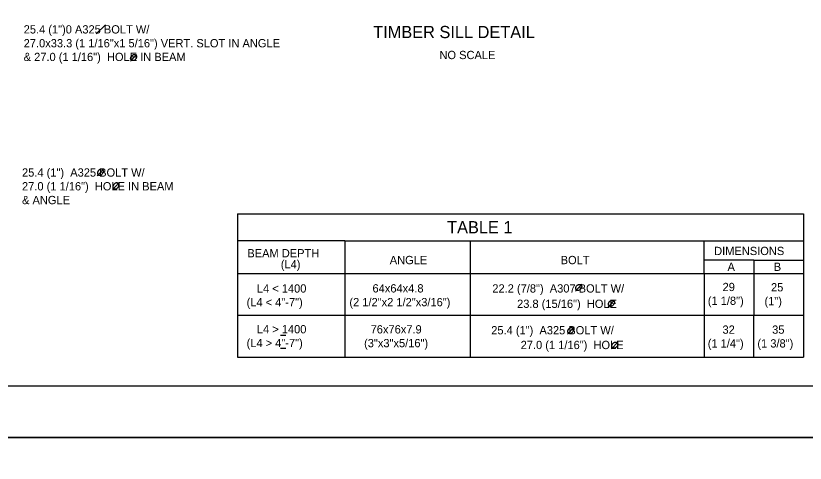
# Model space of a CAD drawing. Extents: x -13 to 81, y -176 to 0.
# Drawn here: x 47.78 to 59.23, y -44.38 to -37.88 of the extents above; entities that cross this region are included whole.
import ezdxf

# ---------------------------------------------------------------- set-up
doc = ezdxf.new("R2010")
doc.units = 0
for name, color, linetype in [('Level 1', 7, 'Continuous'), ('Level 3', 7, 'Continuous'), ('Level 4', 7, 'Continuous'), ('Level 5', 7, 'Continuous'), ('Level 63', 7, 'Continuous')]:
    doc.layers.add(name, color=color, linetype=linetype)

msp = doc.modelspace()

# ---------------------------------------------------------------- linework, layer by layer
at = {"layer": 'Level 1'}
msp.add_lwpolyline([(35.75, -43.25), (67.25, -43.25), (67.25, -22.75), (35.75, -22.75)], close=True, dxfattribs=at)
at = {"layer": 'Level 3'}
for p, q in [((48.952, -38.143), (49.087, -38.008)), ((51.626, -42.518), (51.701, -42.518)), ((51.626, -42.703), (51.701, -42.703))]:
    msp.add_line(p, q, dxfattribs=at)
at = {"layer": 'Level 4'}
for p, q in [((49.447, -38.538), (49.537, -38.44)), ((48.966, -40.203), (49.055, -40.104)), ((49.19, -40.402), (49.28, -40.304)), ((55.902, -41.875), (55.992, -41.777)), ((56.377, -42.106), (56.467, -42.008)), ((55.787, -42.501), (55.877, -42.403)), ((56.425, -42.714), (56.515, -42.616))]:
    msp.add_line(p, q, dxfattribs=at)
for points in [[(49.528, -38.449), (49.521, -38.444), (49.514, -38.442), (49.505, -38.441), (49.5, -38.441), (49.491, -38.443), (49.483, -38.447), (49.478, -38.45), (49.467, -38.458), (49.459, -38.469), (49.454, -38.479), (49.451, -38.488), (49.45, -38.497), (49.451, -38.504), (49.455, -38.515), (49.459, -38.52), (49.466, -38.526), (49.478, -38.529), (49.491, -38.529), (49.508, -38.521), (49.52, -38.511), (49.529, -38.498), (49.535, -38.485), (49.537, -38.47), (49.535, -38.46), (49.528, -38.449)], [(49.046, -40.114), (49.039, -40.109), (49.032, -40.107), (49.023, -40.106), (49.018, -40.106), (49.01, -40.108), (49.002, -40.112), (48.996, -40.115), (48.986, -40.123), (48.977, -40.134), (48.972, -40.144), (48.969, -40.153), (48.969, -40.162), (48.969, -40.169), (48.973, -40.18), (48.977, -40.185), (48.985, -40.191), (48.996, -40.194), (49.009, -40.194), (49.026, -40.186), (49.038, -40.175), (49.047, -40.163), (49.053, -40.149), (49.055, -40.135), (49.053, -40.125), (49.047, -40.114)], [(49.27, -40.313), (49.263, -40.308), (49.256, -40.306), (49.248, -40.305), (49.242, -40.305), (49.234, -40.307), (49.226, -40.311), (49.221, -40.314), (49.21, -40.323), (49.202, -40.333), (49.197, -40.343), (49.194, -40.353), (49.193, -40.361), (49.194, -40.369), (49.197, -40.379), (49.201, -40.385), (49.209, -40.391), (49.22, -40.393), (49.234, -40.393), (49.25, -40.385), (49.262, -40.375), (49.272, -40.362), (49.278, -40.349), (49.28, -40.334), (49.277, -40.325), (49.271, -40.313)], [(55.983, -41.787), (55.975, -41.782), (55.968, -41.78), (55.96, -41.779), (55.955, -41.779), (55.946, -41.781), (55.938, -41.785), (55.933, -41.788), (55.922, -41.796), (55.914, -41.807), (55.909, -41.817), (55.906, -41.826), (55.905, -41.835), (55.906, -41.842), (55.91, -41.853), (55.913, -41.858), (55.921, -41.864), (55.933, -41.867), (55.946, -41.867), (55.963, -41.859), (55.975, -41.848), (55.984, -41.836), (55.99, -41.822), (55.992, -41.808), (55.989, -41.798), (55.983, -41.787)], [(56.458, -42.018), (56.451, -42.012), (56.444, -42.011), (56.435, -42.01), (56.43, -42.01), (56.421, -42.012), (56.413, -42.015), (56.408, -42.018), (56.397, -42.027), (56.389, -42.038), (56.384, -42.048), (56.381, -42.057), (56.38, -42.066), (56.381, -42.073), (56.385, -42.084), (56.389, -42.089), (56.396, -42.095), (56.408, -42.098), (56.421, -42.097), (56.438, -42.09), (56.45, -42.079), (56.459, -42.066), (56.465, -42.053), (56.467, -42.039), (56.465, -42.029), (56.458, -42.018)], [(55.868, -42.413), (55.861, -42.407), (55.854, -42.405), (55.845, -42.404), (55.84, -42.404), (55.831, -42.406), (55.823, -42.41), (55.818, -42.413), (55.807, -42.422), (55.799, -42.432), (55.794, -42.442), (55.791, -42.452), (55.79, -42.46), (55.791, -42.468), (55.795, -42.478), (55.799, -42.484), (55.806, -42.49), (55.818, -42.492), (55.831, -42.492), (55.848, -42.484), (55.86, -42.474), (55.869, -42.461), (55.875, -42.448), (55.877, -42.433), (55.874, -42.424), (55.868, -42.413)], [(56.506, -42.625), (56.498, -42.62), (56.491, -42.618), (56.483, -42.617), (56.478, -42.617), (56.469, -42.619), (56.461, -42.623), (56.456, -42.626), (56.445, -42.634), (56.437, -42.645), (56.432, -42.655), (56.429, -42.664), (56.428, -42.673), (56.429, -42.68), (56.433, -42.691), (56.436, -42.696), (56.444, -42.702), (56.456, -42.705), (56.469, -42.705), (56.486, -42.697), (56.498, -42.687), (56.507, -42.674), (56.513, -42.661), (56.515, -42.646), (56.512, -42.636), (56.506, -42.625)]]:
    msp.add_spline(points, degree=3, dxfattribs=at)
at = {"layer": 'Level 5'}
for p, q in [((51, -40.752), (51, -42.836)), ((51, -40.752), (59.211, -40.752)), ((59.211, -40.752), (59.211, -41.425)), ((52.559, -41.146), (51, -41.146)), ((52.559, -41.146), (52.559, -42.836)), ((52.559, -41.146), (54.374, -41.146)), ((54.374, -41.146), (54.374, -42.836)), ((54.374, -41.146), (59.211, -41.146)), ((57.767, -41.621), (57.767, -41.146)), ((58.489, -41.425), (57.767, -41.425)), ((58.489, -41.425), (59.211, -41.425)), ((58.489, -41.425), (58.489, -41.621)), ((59.211, -41.425), (59.211, -42.836)), ((51, -41.621), (52.559, -41.621)), ((52.559, -41.621), (54.374, -41.621)), ((54.374, -41.621), (57.767, -41.621)), ((57.767, -41.621), (57.767, -42.836)), ((57.767, -41.621), (58.489, -41.621)), ((58.489, -41.621), (59.211, -41.621)), ((58.489, -41.621), (58.489, -42.227)), ((51, -42.227), (52.559, -42.227)), ((52.559, -42.227), (54.374, -42.227)), ((54.374, -42.227), (57.767, -42.227)), ((57.767, -42.227), (58.489, -42.227)), ((58.489, -42.227), (59.211, -42.227)), ((58.489, -42.836), (58.489, -42.227)), ((51, -42.836), (52.559, -42.836)), ((52.559, -42.836), (54.374, -42.836)), ((54.374, -42.836), (57.767, -42.836)), ((57.767, -42.836), (59.211, -42.836))]:
    msp.add_line(p, q, dxfattribs=at)
at = {"layer": 'Level 63'}
for points in [[(34, -44), (68, -44), (68, -22), (34, -22)], [(34, -66), (68, -66), (68, -44), (34, -44)]]:
    msp.add_lwpolyline(points, close=True, dxfattribs=at)

# ---------------------------------------------------------------- texts
at = {"layer": 'Level 3'}
for s, height, p in [('25.4 (1")0 A325 BOLT W/', 0.12, (47.899, -38.136)), ('TIMBER SILL DETAIL', 0.17717, (52.968, -38.203)), ('27.0x33.3 (1 1/16"x1 5/16") VERT. SLOT IN ANGLE', 0.12, (47.899, -38.337)), ('& 27.0 (1 1/16")  HOLE IN BEAM', 0.12, (47.899, -38.536)), ('NO SCALE', 0.12, (53.929, -38.508)), ('25.4 (1")  A325 BOLT W/', 0.12, (47.875, -40.214)), ('27.0 (1 1/16")  HOLE IN BEAM', 0.12, (47.875, -40.414)), ('& ANGLE', 0.12, (47.875, -40.614)), ('TABLE 1', 0.1772, (54.04, -41.037)), ('BEAM DEPTH', 0.12, (51.143, -41.386)), ('DIMENSIONS', 0.12, (57.913, -41.353)), ('(L4)', 0.12, (51.628, -41.546)), ('ANGLE', 0.12, (53.208, -41.485)), ('BOLT', 0.12, (55.687, -41.485)), ('A', 0.12, (58.107, -41.583)), ('B', 0.12, (58.778, -41.583)), ('L4 < 1400', 0.12, (51.281, -41.898)), ('64x64x4.8', 0.12, (52.958, -41.896)), ('22.2 (7/8")  A307 BOLT W/', 0.12, (54.696, -41.897)), ('29', 0.12, (58.035, -41.876)), ('25', 0.12, (58.738, -41.88)), ('(L4 < 4"-7")', 0.12, (51.132, -42.098)), ('(2 1/2"x2 1/2"x3/16")', 0.12, (52.623, -42.096)), ('23.8 (15/16")  HOLE', 0.12, (55.055, -42.12)), ('(1 1/8")', 0.12, (57.821, -42.076)), ('(1")', 0.12, (58.643, -42.081)), ('L4 > 1400', 0.12, (51.281, -42.489)), ('76x76x7.9', 0.12, (52.931, -42.491)), ('25.4 (1")  A325 BOLT W/', 0.12, (54.68, -42.504)), ('32', 0.12, (58.034, -42.495)), ('35', 0.12, (58.754, -42.495)), ('(L4 > 4"-7")', 0.12, (51.132, -42.689)), ('(3"x3"x5/16")', 0.12, (52.836, -42.691)), ('(1 1/4")', 0.12, (57.82, -42.695)), ('(1 3/8")', 0.12, (58.54, -42.695)), ('27.0 (1 1/16")  HOLE', 0.12, (55.107, -42.718))]:
    msp.add_text(s, height=height, dxfattribs=at).set_placement(p)

doc.saveas('drawing.dxf')
